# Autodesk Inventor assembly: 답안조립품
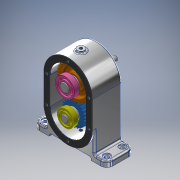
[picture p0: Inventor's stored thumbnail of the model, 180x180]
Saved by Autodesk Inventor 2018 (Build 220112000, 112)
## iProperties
Created: 2021-05
Part Number: 답안조립품
Material: 일반
Document SubType Name: Assembly
Designer: Admin
Author: Admin
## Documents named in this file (14)
- C:\Users\Admin\Desktop\710509V1011\답안조립품.iam
- C:\Users\Admin\Desktop\710509V1011\본체.ipt
- C:\Users\Admin\Desktop\710509V1011\축 A.ipt
- C:\Users\Admin\Desktop\710509V1011\베어링 6001.ipt
- 베어링 6001.ipt
- C:\Users\Admin\Desktop\710509V1011\베어링 6002.ipt
- 베어링 6002.ipt
- C:\Users\Admin\Desktop\710509V1011\칼라.ipt
- C:\Users\Admin\Desktop\710509V1011\축 B.ipt
- C:\Users\Admin\Desktop\710509V1011\스퍼기어 A.ipt
- C:\Users\Admin\Desktop\710509V1011\키 5 x 5 x 12.ipt
- C:\Users\Admin\Desktop\710509V1011\키 4 x 4 x 12.ipt
- C:\Users\Admin\Desktop\710509V1011\스퍼기어 B.ipt
- C:\Users\Admin\Desktop\710509V1011\개스킷 A.ipt
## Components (1 placed, 1 different names)
1. 개스킷 A:1
